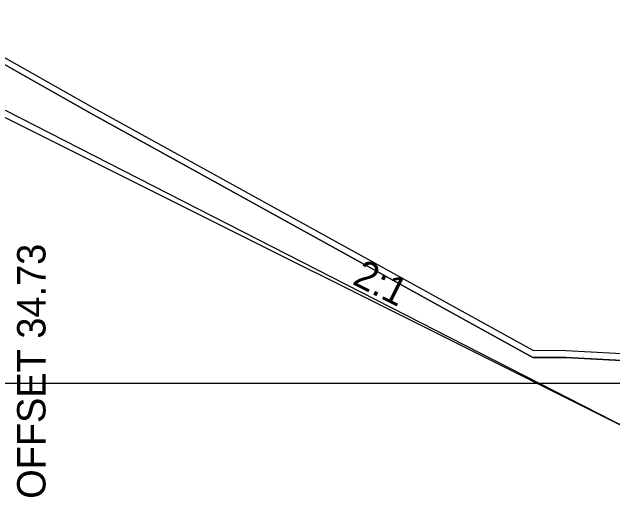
# Model space of a CAD drawing. Extents: x -120 to 2876, y -25 to 8560.
# Drawn here: x 184.97 to 206.14, y 6495.99 to 6513.09 of the extents above; entities that cross this region are included whole.
import ezdxf

# ---------------------------------------------------------------- set-up
doc = ezdxf.new("R2010")
doc.units = 0
for name, color, linetype in [('DESIGN - EARTHWORK - Shapes', 7, 'Continuous'), ('DESIGN - SHEET - Light Grid', 7, 'Continuous'), ('DESIGN - TYPICAL - Finished Grade and Subgrade', 7, 'Continuous'), ('DESIGN - TYPICAL - Finished Grade Slopes Text', 7, 'Continuous'), ('DESIGN - TYPICAL - Subgrade Tie Text', 7, 'Continuous'), ('SURVEY - GROUND - Bottom of Topsoil Layer', 7, 'Continuous'), ('SURVEY - GROUND - Top of Ground', 7, 'Continuous')]:
    doc.layers.add(name, color=color, linetype=linetype)

msp = doc.modelspace()

# ---------------------------------------------------------------- linework, layer by layer
at = {"layer": 'DESIGN - EARTHWORK - Shapes'}
for points in [[(149.209, 6512.651), (150, 6512.969), (150.307, 6513.092), (177.21, 6512.992), (177.527, 6512.994), (180.339, 6512.713), (182.691, 6512.622), (187.835, 6509.713), (203.323, 6501.166), (204.485, 6501.156), (209.765, 6500.874), (211.355, 6502.129), (211.355, 6501.879), (209.765, 6500.624), (204.485, 6500.906), (203.323, 6500.916), (187.835, 6509.463), (182.691, 6512.372), (180.339, 6512.463), (177.527, 6512.744), (177.21, 6512.742), (150.307, 6512.842), (150, 6512.719), (149.766, 6512.625)], [(174, 6511.486), (176, 6511.392), (179.417, 6511.231), (184.145, 6509.655), (207.073, 6498.191), (208.855, 6497.3), (211.355, 6497.3), (211.355, 6501.879), (209.765, 6500.624), (204.485, 6500.906), (203.323, 6500.916), (187.835, 6509.463), (182.691, 6512.372), (180.339, 6512.463), (177.527, 6512.744), (177.21, 6512.742), (150.307, 6512.842), (150, 6512.719), (149.766, 6512.625), (150, 6512.614), (159, 6512.191)]]:
    msp.add_lwpolyline(points, close=True, dxfattribs=at)
at = {"layer": 'DESIGN - SHEET - Light Grid'}
msp.add_line((150, 6500), (300, 6500), dxfattribs=at)
at = {"layer": 'DESIGN - TYPICAL - Finished Grade and Subgrade'}
msp.add_line((184.725, 6509.628), (207.073, 6498.191), dxfattribs=at)
at = {"layer": 'SURVEY - GROUND - Bottom of Topsoil Layer'}
for p, q in [((182.691, 6512.372), (187.835, 6509.463)), ((187.835, 6509.463), (203.323, 6500.916)), ((203.323, 6500.916), (204.485, 6500.906)), ((204.485, 6500.906), (209.765, 6500.624))]:
    msp.add_line(p, q, dxfattribs=at)
at = {"layer": 'SURVEY - GROUND - Top of Ground'}
msp.add_lwpolyline([(117.566, 6507.83), (122.936, 6507.931), (125.005, 6507.948), (130.972, 6507.69), (136.983, 6507.424), (138.571, 6507.809), (139.306, 6508.302), (139.811, 6508.64), (145.848, 6511.299), (150, 6512.969), (150.307, 6513.092), (177.21, 6512.992), (177.527, 6512.994), (180.339, 6512.713), (182.691, 6512.622), (187.835, 6509.713), (203.323, 6501.166), (204.485, 6501.156), (209.765, 6500.874), (211.67, 6502.378), (212.597, 6503.071), (231.568, 6504.209)], dxfattribs=at)

# ---------------------------------------------------------------- texts
at = {"layer": 'DESIGN - TYPICAL - Finished Grade Slopes Text'}
msp.add_text('2:1', height=1, rotation=333.4349, dxfattribs=at).set_placement((196.916, 6503.515))
at = {"layer": 'DESIGN - TYPICAL - Subgrade Tie Text'}
msp.add_text('OFFSET 34.73', height=1, rotation=90, dxfattribs=at).set_placement((186.145, 6495.929))

doc.saveas('drawing.dxf')
